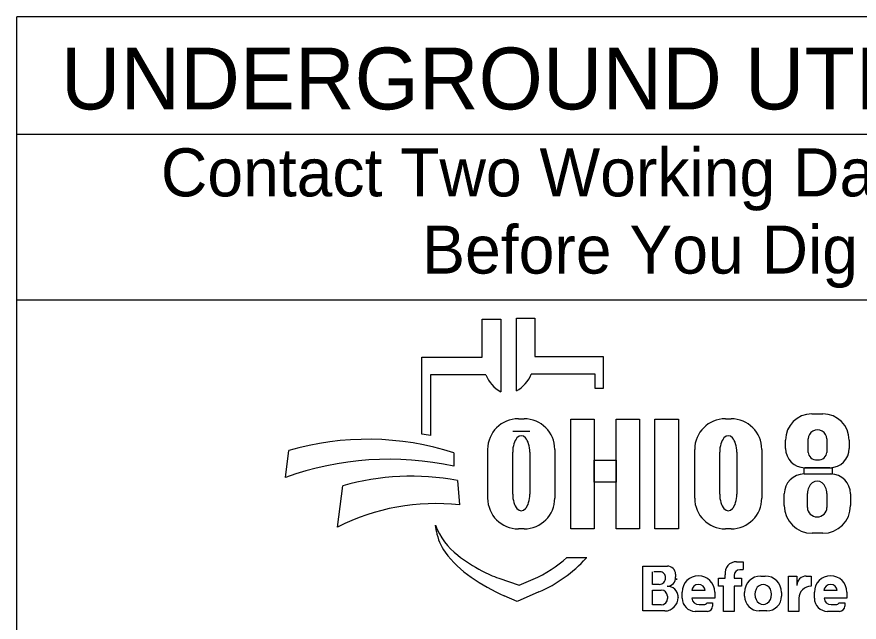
# Model space of a CAD drawing. Extents: x 0 to 44, y -23.8 to 22.
# Drawn here: x 2.378 to 4.831, y 1.33 to 3.094 of the extents above; entities that cross this region are included whole.
import ezdxf

# ---------------------------------------------------------------- set-up
doc = ezdxf.new("R2010")
doc.units = 0
doc.layers.add('SH_Data', color=7, linetype='Continuous')
doc.layers.add('SH_Text', color=7, linetype='Continuous')

msp = doc.modelspace()

# ---------------------------------------------------------------- linework, layer by layer
at = {"layer": 'SH_Data'}
for p, q in [((2.3775, 0.7566), (2.3775, 3.0941)), ((6.6275, 3.0941), (2.3775, 3.0941)), ((2.3775, 2.7525), (6.6275, 2.7525)), ((2.3775, 2.2691), (6.6275, 2.2691))]:
    msp.add_line(p, q, dxfattribs=at)
at = {"layer": 'SH_Text'}
for p, q in [((3.7335, 2.1021), (3.7335, 2.2135)), ((3.7335, 2.2135), (3.7872, 2.2135)), ((3.7872, 2.2135), (3.7872, 2.0015)), ((3.8329, 2.0038), (3.8329, 2.2159)), ((3.8329, 2.2159), (3.8865, 2.2159)), ((3.8865, 2.2159), (3.8865, 2.1044)), ((3.5576, 1.8782), (3.5576, 2.1021)), ((3.5576, 2.1021), (3.7335, 2.1021)), ((3.8865, 2.1044), (4.0857, 2.1044)), ((4.0857, 2.1044), (4.0857, 2.0106)), ((3.5828, 2.0506), (3.5828, 1.8738)), ((3.7439, 2.0506), (3.5828, 2.0506)), ((4.0625, 2.0529), (3.8761, 2.0529)), ((4.0625, 2.0106), (4.0625, 2.0529)), ((4.0857, 2.0106), (4.0625, 2.0106)), ((3.8385, 1.9229), (3.8551, 1.9229)), ((4.4416, 1.9229), (4.4581, 1.9229)), ((4.6931, 1.9369), (4.7258, 1.9369)), ((3.8718, 1.8859), (3.822, 1.8859)), ((4.6168, 1.8363), (4.6168, 1.8606)), ((4.683, 1.8249), (4.683, 1.8642)), ((4.7371, 1.8642), (4.7371, 1.8249)), ((4.8022, 1.8606), (4.8022, 1.8363)), ((3.1602, 1.7519), (3.1696, 1.83)), ((3.6509, 1.8235), (3.6509, 1.7847)), ((3.7491, 1.6914), (3.7491, 1.8334)), ((3.822, 1.7028), (3.822, 1.8251)), ((3.8718, 1.8251), (3.8718, 1.7028)), ((3.9445, 1.8334), (3.9445, 1.6914)), ((4.3521, 1.6914), (4.3521, 1.8334)), ((4.425, 1.7028), (4.425, 1.8251)), ((4.4748, 1.8251), (4.4748, 1.7028)), ((4.5476, 1.8334), (4.5476, 1.6914)), ((4.7462, 1.7803), (4.6728, 1.7803)), ((3.6608, 1.7429), (3.6671, 1.6719)), ((4.671, 1.762), (4.7483, 1.762)), ((3.312, 1.6073), (3.3267, 1.7275)), ((4.6131, 1.67), (4.6131, 1.7041)), ((4.6806, 1.6641), (4.6806, 1.705)), ((4.7374, 1.705), (4.7374, 1.6641)), ((4.8062, 1.7041), (4.8062, 1.67)), ((3.5997, 1.5944), (3.5967, 1.6124)), ((3.8551, 1.6019), (3.8385, 1.6019)), ((4.4581, 1.6019), (4.4416, 1.6019)), ((4.7252, 1.5891), (4.6941, 1.5891)), ((3.98, 1.5186), (4.0375, 1.5186)), ((4.4739, 1.5063), (4.4934, 1.5063)), ((4.4934, 1.5063), (4.4934, 1.4833)), ((4.2013, 1.3628), (4.2013, 1.4935)), ((4.2013, 1.4935), (4.2725, 1.4935)), ((4.2293, 1.4401), (4.2293, 1.477)), ((4.2545, 1.477), (4.2332, 1.477)), ((4.4934, 1.4829), (4.4832, 1.4829)), ((3.7816, 1.4582), (3.841, 1.4377)), ((3.841, 1.4377), (3.8821, 1.4555)), ((4.2963, 1.4698), (4.2963, 1.4619)), ((4.4213, 1.435), (4.4213, 1.4579)), ((4.4213, 1.4579), (4.4406, 1.4579)), ((4.4406, 1.4579), (4.4406, 1.4684)), ((4.4667, 1.4664), (4.4667, 1.4579)), ((4.4667, 1.4579), (4.4883, 1.4579)), ((4.4883, 1.4579), (4.4883, 1.435)), ((4.5451, 1.4645), (4.5573, 1.4645)), ((4.6254, 1.3616), (4.6254, 1.4643)), ((4.6254, 1.4643), (4.6499, 1.4643)), ((4.6499, 1.4643), (4.6499, 1.4374)), ((4.6772, 1.4643), (4.691, 1.4643)), ((4.691, 1.4643), (4.691, 1.4346)), ((4.2487, 1.4401), (4.2293, 1.4401)), ((4.2293, 1.3806), (4.2293, 1.4235)), ((4.2293, 1.4235), (4.2548, 1.4235)), ((4.4362, 1.435), (4.4213, 1.435)), ((4.4362, 1.3616), (4.4362, 1.435)), ((4.4883, 1.435), (4.4667, 1.435)), ((4.4667, 1.435), (4.4667, 1.3616)), ((3.835, 1.3907), (3.7976, 1.4071)), ((3.8983, 1.4181), (3.835, 1.3907)), ((4.2729, 1.4054), (4.2729, 1.399)), ((4.3043, 1.4025), (4.3043, 1.4021)), ((4.3159, 1.3996), (4.3159, 1.418)), ((4.3824, 1.422), (4.3439, 1.422)), ((4.4104, 1.4003), (4.344, 1.4003)), ((4.4104, 1.418), (4.4104, 1.4003)), ((4.4973, 1.4059), (4.4973, 1.4167)), ((4.6051, 1.4167), (4.6051, 1.4059)), ((4.6559, 1.3997), (4.6559, 1.3616)), ((4.7008, 1.3996), (4.7008, 1.418)), ((4.7674, 1.422), (4.7288, 1.422)), ((4.7953, 1.4003), (4.7289, 1.4003)), ((4.7953, 1.418), (4.7953, 1.4003)), ((4.2546, 1.3806), (4.2293, 1.3806)), ((4.3649, 1.3811), (4.379, 1.3811)), ((4.3876, 1.3867), (4.4045, 1.3867)), ((4.4045, 1.3867), (4.4045, 1.3768)), ((4.7498, 1.3811), (4.7639, 1.3811)), ((4.7725, 1.3867), (4.7894, 1.3867)), ((4.7894, 1.3867), (4.7894, 1.3768)), ((4.265, 1.3628), (4.2013, 1.3628)), ((4.3892, 1.3616), (4.3538, 1.3616)), ((4.4667, 1.3616), (4.4362, 1.3616)), ((4.5623, 1.3631), (4.5401, 1.3631)), ((4.6559, 1.3616), (4.6254, 1.3616)), ((4.7742, 1.3616), (4.7388, 1.3616))]:
    msp.add_line(p, q, dxfattribs=at)
for points in [[(3.991, 1.9218), (4.0589, 1.9218), (4.0589, 1.6019), (3.991, 1.6019)], [(4.1231, 1.9218), (4.1911, 1.9218), (4.1911, 1.6019), (4.1231, 1.6019)], [(4.2364, 1.9218), (4.3052, 1.9218), (4.3052, 1.6019), (4.2364, 1.6019)], [(4.0589, 1.8019), (4.1231, 1.8019), (4.1231, 1.7379), (4.0589, 1.7379)], [(4.6706, 1.7803), (4.7523, 1.7803), (4.7523, 1.7618), (4.6706, 1.7618)]]:
    msp.add_lwpolyline(points, close=True, dxfattribs=at)
for centre, radius, start, end in [((3.8353, 2.0874), 0.0985, 201.9296, 240.7469), ((3.7847, 2.0897), 0.0985, 299.2531, 338.0704), ((3.8385, 1.8334), 0.0895, 90, 180), ((3.8551, 1.8334), 0.0895, 0, 90), ((4.4416, 1.8334), 0.0895, 90, 180), ((4.4581, 1.8334), 0.0895, 0, 90), ((4.6931, 1.8606), 0.0763, 90, 180), ((4.7258, 1.8606), 0.0763, 0, 90), ((3.4295, 1.0692), 0.8191, 79.2074, 81.0007), ((3.3997, 1.0439), 0.8191, 72.1402, 106.3144), ((4.6728, 1.8363), 0.056, 180, 270), ((4.7462, 1.8363), 0.056, 270, 0), ((3.4628, 0.9128), 0.8919, 77.8238, 109.8274), ((3.5267, 1.0231), 0.7322, 79.44, 105.8467), ((4.671, 1.7041), 0.0579, 90, 180), ((4.7483, 1.7041), 0.0579, 0, 90), ((3.5987, 1.0399), 0.6357, 83.8248, 116.8021), ((3.8385, 1.6914), 0.0895, 180, 270), ((3.8551, 1.6914), 0.0895, 270, 0), ((4.4416, 1.6914), 0.0895, 180, 270), ((4.4581, 1.6914), 0.0895, 270, 0), ((4.6941, 1.67), 0.081, 180, 270), ((4.7252, 1.67), 0.081, 270, 0), ((3.7841, 1.6845), 0.2008, 201.0457, 232.5314), ((3.741, 1.6185), 0.1433, 189.6817, 216.0884), ((3.8747, 1.716), 0.3088, 216.0884, 235.7167), ((3.9766, 1.9357), 0.5173, 232.5314, 241.794), ((3.7387, 1.786), 0.3602, 293.4582, 312.0712), ((3.7387, 1.786), 0.401, 293.4582, 317.8286), ((4.4739, 1.4728), 0.0335, 90, 187.5187), ((3.8914, 1.7769), 0.3371, 241.794, 250.9821), ((4.2505, 1.4601), 0.0169, 357.8325, 90), ((4.2725, 1.4698), 0.0238, 0, 90), ((4.4832, 1.4664), 0.0165, 90, 180), ((4.0412, 1.9602), 0.6044, 235.7167, 246.2325), ((4.2487, 1.4588), 0.0187, 270, 2.0582), ((4.2721, 1.4591), 0.0243, 270, 6.6529), ((4.2827, 1.4576), 0.0175, 347.4023, 0), ((4.3631, 1.418), 0.0473, 0, 180), ((4.5451, 1.4167), 0.0478, 90, 180), ((4.5573, 1.4167), 0.0478, 0, 90), ((4.6768, 1.4374), 0.0269, 89.2449, 180), ((4.7481, 1.418), 0.0473, 0, 180), ((4.2548, 1.4054), 0.0181, 0, 90), ((4.2722, 1.4027), 0.0321, 4.0748, 90), ((4.3632, 1.421), 0.0193, 2.9632, 177.0368), ((4.6908, 1.3997), 0.0349, 89.6033, 180), ((4.7481, 1.421), 0.0193, 2.9632, 177.0368), ((4.2546, 1.399), 0.0184, 270, 0), ((4.265, 1.4021), 0.0393, 270, 0), ((4.2714, 1.4025), 0.033, 0, 11.7502), ((4.3538, 1.3996), 0.038, 180, 270), ((4.3649, 1.4021), 0.021, 184.827, 270), ((4.5401, 1.4059), 0.0428, 180, 270), ((4.5623, 1.4059), 0.0428, 270, 0), ((4.7388, 1.3996), 0.038, 180, 270), ((4.7498, 1.4021), 0.021, 184.827, 270), ((4.379, 1.3905), 0.00938, 270, 335.9979), ((4.3892, 1.3768), 0.0152, 270, 0), ((4.7639, 1.3905), 0.00938, 270, 335.9979), ((4.7742, 1.3768), 0.0152, 270, 0)]:
    msp.add_arc(centre, radius, start, end, dxfattribs=at)
for centre, major_axis, ratio, start_param, end_param in [((4.71, 1.8642), (0.0271, 0), 0.969373, 0, 3.141593), ((3.8469, 1.8251), (0, 0.0484), 0.514403, 4.712389, 7.853982), ((4.4499, 1.8251), (0, 0.0484), 0.514403, 4.712389, 7.853982), ((4.71, 1.8249), (0.0271, 0), 0.818453, 3.141593, 6.283185), ((4.709, 1.705), (0, 0.0358), 0.794529, 4.712389, 7.853982), ((3.8469, 1.7028), (0, 0.0484), 0.514403, 1.570796, 4.712389), ((4.4499, 1.7028), (0, 0.0484), 0.514403, 1.570796, 4.712389), ((4.709, 1.6641), (0.0284, 0), 0.959837, 3.141593, 6.283185), ((4.5517, 1.4113), (0, 0.029), 0.832186, 4.712389, 7.853982), ((4.5517, 1.4113), (0, 0.0302), 0.797287, 1.570796, 4.712389)]:
    msp.add_ellipse(centre, major_axis=major_axis, ratio=ratio, start_param=start_param, end_param=end_param, dxfattribs=at)

# ---------------------------------------------------------------- texts
for s, height, p in [('UNDERGROUND UTILITIES', 0.18, (2.5057, 2.8244)), ('Contact Two Working Days', 0.14, (2.7972, 2.5709)), ('Before You Dig', 0.14, (3.5583, 2.3459))]:
    msp.add_text(s, height=height, dxfattribs=at).set_placement(p)

doc.saveas('drawing.dxf')
